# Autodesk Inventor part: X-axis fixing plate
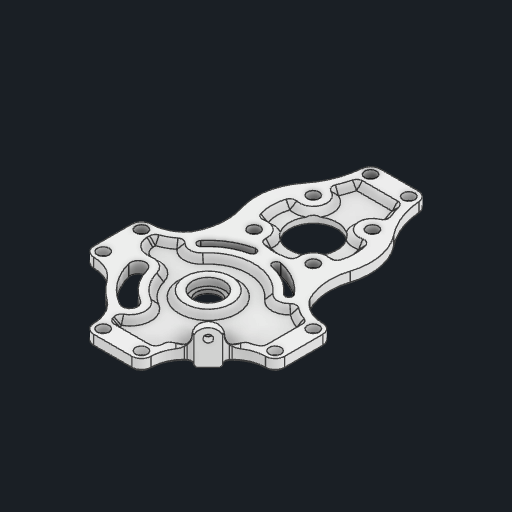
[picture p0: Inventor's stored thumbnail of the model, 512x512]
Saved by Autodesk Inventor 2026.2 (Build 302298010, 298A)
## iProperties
Created: 2026-04
Part Number: X-axis fixing plate
Material: PBT 플라스틱
Document SubType Name: Modeling
Designer: work
Density: 1.31 g/cm^3
Appearance: 매끄러움 - 흰색
Author: work
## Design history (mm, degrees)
sketch "스케치1"
  geometry: L1 (0, 0)-(0, -55); L2 (-15.5, -39.5)-(15.5, -39.5); L3 (15.5, -39.5)-(15.5, -70.5); L4 (15.5, -70.5)-(-15.5, -70.5); L5 (-15.5, -70.5)-(-15.5, -39.5); L6 (-15.5, -39.5)-(15.5, -70.5); L7 (15.5, -39.5)-(-15.5, -70.5); L8 (0, 0)-(22.981, -19.284); L9 (0, 0)-(30, 0); L10 (0, 0)-(6.237, -29.344); L11 (0, 0)-(-6.237, -29.344); L12 (-10, -95)-(10, -95); L13 (0, -55)-(0, -95); L14 (0, 0)-(45, 0); L15 (-10, -95)-(10, -95); L16 (-10, -100)-(10, -100); L17 (10, -90)-(-10, -90); L18 (10, 50)-(-10, 50); L19 (-10, 45)-(10, 45); L20 (-10, 45)-(10, 45); L21 (-10, 40)-(10, 40); L22 (0, 0)-(0, 45); L23 (0, 0)-(-45, 0); L24 (-45, -10)-(-45, 10); L25 (-40, -10)-(-40, 10); L26 (-50, 10)-(-50, -10); L27 (-45, -10)-(-45, 10); L28 (0, 0)-(0, -45); L29 (10, -45)-(-10, -45); L30 (10, -40)-(-10, -40); L31 (-10, -50)-(10, -50); L32 (10, -45)-(-10, -45); L33 (0, 0)-(45, 0); L34 (45, 10)-(45, -10); L35 (40, 10)-(40, -10); L36 (50, -10)-(50, 10); L37 (45, 10)-(45, -10); L38 (0, 0)-(-26.87, 26.87); L39 (-22.627, 31.113)-(-31.113, 22.627); L40 (-31.113, 22.627)-(-28.991, 20.506); L41 (-28.991, 20.506)-(-20.506, 28.991); L42 (-20.506, 28.991)-(-22.627, 31.113); L43 (0, 0)-(28.978, 7.765); L44 (0, 0)-(15, 25.981); C1 r 2.5 at (0, 0); C2 r 8.25 at (0, 0); C3 r 6.25 at (0, 0); C4 r 12.5 at (0, -55); C5 r 2 at (15.5, -39.5); C6 r 2 at (-15.5, -70.5); C7 r 2 at (15.5, -70.5); C8 r 2 at (-15.5, -39.5); C9 r 22 at (0, 0); C10 r 2 at (10, -95); C11 r 2 at (-10, -95); C12 r 2 at (10, 45); C13 r 2 at (-10, 45); C14 r 2 at (-45, 10); C15 r 2 at (-45, -10); C16 r 2 at (-10, -45); C17 r 2 at (10, -45); C18 r 2 at (45, -10); C19 r 2 at (45, 10); A1 r 30 centre (0, 0) between (6.237, -29.344) and (22.981, -19.284); A2 r 32 centre (0, 0) between (6.653, -31.301) and (24.513, -20.569); A3 r 28 centre (0, 0) between (5.822, -27.388) and (21.449, -17.998); A4 r 2 centre (6.237, -29.344) between (5.822, -27.388) and (6.653, -31.301); A5 r 2 centre (22.981, -19.284) between (24.513, -20.569) and (21.449, -17.998); A6 r 28 centre (0, 0) between (-21.449, -17.998) and (-5.822, -27.388); A7 r 30 centre (0, 0) between (-22.981, -19.284) and (-6.237, -29.344); A8 r 2 centre (-6.237, -29.344) between (-6.653, -31.301) and (-5.822, -27.388); A9 r 32 centre (0, 0) between (-24.513, -20.569) and (-6.653, -31.301); A10 r 2 centre (-22.981, -19.284) between (-21.449, -17.998) and (-24.513, -20.569); A11 r 38 centre (0, 0) between (22.258, 30.799) and (-26.87, 26.87); A12 r 30 centre (0, -55) between (-23.514, -73.63) and (28.562, -45.823); A13 r 5 centre (-10, -95) between (-10, -90) and (-10, -100); A14 r 5 centre (10, -95) between (10, -100) and (10, -90); A15 r 40 centre (-54.866, -98.471) between (-14.985, -95.386) and (-23.514, -73.63); A16 r 40 centre (54.866, -98.471) between (23.514, -73.63) and (14.985, -95.386); A17 r 5 centre (-10, 45) between (-10, 50) and (-10, 40); A18 r 5 centre (10, 45) between (10, 40) and (10, 50); A19 r 17.522 centre (32.522, 45) between (15, 45) and (22.258, 30.799); A20 r 17.522 centre (-32.522, 45) between (-22.258, 30.799) and (-15, 45); A21 r 17.522 centre (-45, -32.522) between (-30.799, -22.258) and (-45, -15); A22 r 5 centre (-45, -10) between (-50, -10) and (-40, -10); A23 r 5 centre (-45, 10) between (-40, 10) and (-50, 10); A24 r 17.522 centre (-45, 32.522) between (-45, 15) and (-30.799, 22.258); A25 r 17.522 centre (32.522, -45) between (22.258, -30.799) and (15, -45); A26 r 5 centre (10, -45) between (10, -50) and (10, -40); A27 r 5 centre (-10, -45) between (-10, -40) and (-10, -50); A28 r 17.522 centre (-32.522, -45) between (-15, -45) and (-22.258, -30.799); A29 r 17.522 centre (45, 32.522) between (30.799, 22.258) and (45, 15); A30 r 5 centre (45, 10) between (50, 10) and (40, 10); A31 r 5 centre (45, -10) between (40, -10) and (50, -10); A32 r 17.522 centre (45, -32.522) between (45, -15) and (30.799, -22.258); A33 r 30 centre (57.124, -36.646) between (30.799, -22.258) and (28.562, -45.823); A34 r 30 centre (-57.124, -36.646) between (-28.562, -45.823) and (-30.799, -22.258); A35 r 30 centre (0, 0) between (28.978, 7.765) and (15, 25.981); A36 r 34 centre (0, 0) between (32.841, 8.8) and (17, 29.445); A37 r 26 centre (0, 0) between (25.114, 6.729) and (13, 22.517); A38 r 4 centre (28.978, 7.765) between (25.114, 6.729) and (32.841, 8.8); A39 r 4 centre (15, 25.981) between (17, 29.445) and (13, 22.517); 17 further points
  constraints: 98 end point, 80 point on circle, 58 centre point, 23 coincident, 21 tangent, 14 symmetric about line, 8 midpoint, 7 equal length, 5 horizontal, 5 perpendicular, 3 vertical, 2 point on line, 121 other
  dimensions: "d0" = 5 diameter of C1; "d1" = 16.5 diameter of C2; "d2" = 2 radial gap between concentric circles of C2 C3; "d3" = 55 distance of L1.start L1.end; "d4" = 25 diameter of C4; "d5" = 31 distance of L3.end L4.end; "d6" = 31 distance of L2.end L3.end; "d7" = 4 diameter of C5; "d9" = 4 diameter of C6; "d10" = 4 diameter of C7; "d11" = 4 diameter of C8; "d14" = 44 diameter of C9; "d15" = 30 radius of A1; "d16" = 40 deg angle of L8 L9; "d17" = 38 deg angle of L10 L8; "d18" = 4 diameter of A4; "d19" = 8 radial gap between concentric circles of A11 A1; "d20" = 60 diameter of A12; "d21" = 20 distance of L12.start L12.end; "d22" = 45 distance of L14.start L14.end; "d23" = 40 distance of L13.start L13.end; "d24" = 4 diameter of C10; "d25" = 4 diameter of C11; "d26" = 5 radius of A14; "d27" = 40 radius of A15; "d28" = 20 distance of L20.start L20.end; "d29" = 4 diameter of C12; "d30" = 4 diameter of C13; "d31" = 5 radius of A18; "d32" = 45 distance of L14.start L22.end; "d35" = 360 deg dimension on C9.centre L22.end (derived); "d37" = 30 radius of A33; "d38" = 45 deg angle of L22 L38; "d39" = 12 distance of L40.end L41.end; "d40" = 3 distance of L39.end L40.end; "d41" = 30 radius of A35; "d42" = 45 deg angle of L43 L44; "d43" = 8 diameter of A38; "d44" = 30 deg angle of L22 L44
  node "스케치 - 원형 패턴1" dims "d35" = 360 deg (derived)
extrude "돌출1" new body sketch "스케치1" distance "d45" = 6; taper "d46" = 0 deg
extrude "돌출2" join sketch "스케치1" distance "d47" = 18; taper "d48" = 0 deg
extrude "돌출3" join sketch "스케치1" distance "d49" = 2; taper "d50" = 0 deg
sketch "스케치2"
  geometry: L1 (-50, 10)-(-50, -10) reference; L2 (-10, -50)-(10, -50) reference; L3 (22.29, -30.776)-(20.506, -28.991) reference; L4 (20.506, -28.991)-(28.991, -20.506) reference; L5 (28.991, -20.506)-(30.776, -22.29) reference; L6 (50, -10)-(50, 10) reference; L7 (10, 100)-(-10, 100) reference; C1 r 2 at (10, 95) reference; C2 r 2 at (-10, 95) reference; C3 r 2 at (10, -45) reference; C4 r 2 at (-10, -45) reference; C5 r 2 at (45, 10) reference; C6 r 2 at (45, -10) reference; C7 r 2 at (-45, -10) reference; C8 r 2 at (-45, 10) reference; C9 r 12.5 at (0, 55) reference; C10 r 2 at (-15.5, 39.5) reference; C11 r 2 at (15.5, 70.5) reference; C12 r 2 at (-15.5, 70.5) reference; C13 r 2 at (15.5, 39.5) reference; C14 r 8.25 at (0, 0) reference; A1 r 17.522 centre (-45, 32.522) between (-45, 15) and (-30.799, 22.258) reference; A2 r 5 centre (-45, 10) between (-45, 15) and (-50, 10) reference; A3 r 5 centre (-45, -10) between (-50, -10) and (-45, -15) reference; A4 r 17.522 centre (-45, -32.522) between (-30.799, -22.258) and (-45, -15) reference; A5 r 38 centre (0, 0) between (-30.799, -22.258) and (-22.258, -30.799) reference; A6 r 17.522 centre (-32.522, -45) between (-15, -45) and (-22.258, -30.799) reference; A7 r 5 centre (-10, -45) between (-15, -45) and (-10, -50) reference; A8 r 5 centre (10, -45) between (10, -50) and (15, -45) reference; A9 r 17.522 centre (32.522, -45) between (22.258, -30.799) and (15, -45) reference; A10 r 38 centre (0, 0) between (22.258, -30.799) and (22.29, -30.776) reference; A11 r 38 centre (0, 0) between (30.776, -22.29) and (30.799, -22.258) reference; A12 r 17.522 centre (45, -32.522) between (45, -15) and (30.799, -22.258) reference; A13 r 5 centre (45, -10) between (45, -15) and (50, -10) reference; A14 r 5 centre (45, 10) between (50, 10) and (45, 15) reference; A15 r 17.522 centre (45, 32.522) between (30.799, 22.258) and (45, 15) reference; A16 r 30 centre (57.124, 36.646) between (28.562, 45.823) and (30.799, 22.258) reference; A17 r 30 centre (0, 55) between (28.562, 45.823) and (23.514, 73.63) reference; A18 r 40 centre (54.866, 98.471) between (14.985, 95.386) and (23.514, 73.63) reference; A19 r 5 centre (10, 95) between (14.985, 95.386) and (10, 100) reference; A20 r 5 centre (-10, 95) between (-10, 100) and (-14.985, 95.386) reference; A21 r 40 centre (-54.866, 98.471) between (-23.514, 73.63) and (-14.985, 95.386) reference; A22 r 30 centre (0, 55) between (-23.514, 73.63) and (-28.562, 45.823) reference; A23 r 32 centre (0, 0) between (24.513, 20.569) and (6.653, 31.301) reference; A24 r 2 centre (22.981, 19.284) between (21.449, 17.998) and (24.513, 20.569) reference; A25 r 28 centre (0, 0) between (21.449, 17.998) and (5.822, 27.388) reference; A26 r 2 centre (6.237, 29.344) between (6.653, 31.301) and (5.822, 27.388) reference; A27 r 32 centre (0, 0) between (-6.653, 31.301) and (-24.513, 20.569) reference; A28 r 2 centre (-6.237, 29.344) between (-5.822, 27.388) and (-6.653, 31.301) reference; A29 r 28 centre (0, 0) between (-5.822, 27.388) and (-21.449, 17.998) reference; A30 r 2 centre (-22.981, 19.284) between (-24.513, 20.569) and (-21.449, 17.998) reference; A31 r 26 centre (0, 0) between (-25.114, -6.729) and (-13, -22.517) reference; A32 r 4 centre (-15, -25.981) between (-17, -29.445) and (-13, -22.517) reference; A33 r 34 centre (0, 0) between (-32.841, -8.8) and (-17, -29.445) reference; A34 r 4 centre (-28.978, -7.765) between (-25.114, -6.729) and (-32.841, -8.8) reference; A35 r 30 centre (-57.124, 36.646) between (-30.799, 22.258) and (-28.562, 45.823) reference; 11 further points
  constraints: 10 coincident
hole "구멍1" sketch "스케치2" at (-10, -45), (10, -45), (-45, -10), (-45, 10), (15.5, 39.5), (-15.5, 39.5), (15.5, 70.5), (-15.5, 70.5), (10, 95), (-10, 95), (45, 10), (45, -10) diameter "d51" = 4; stored, may be unused: countersink angle "d55" = 90 deg, drill point angle "d57" = 0 deg; dims "d52" = 6, "d53" = 6.2, "d54" = 4, "d56" = 8
sketch "스케치3"
  geometry: L1 (-6, 0)-(-6, 18); L2 (-12, 18)-(0, 18) reference; C1 r 2 at (-6, 13)
  constraints: 2 end point, 1 centre point, 1 midpoint, 1 point on line
  dimensions: "d58" = 4 diameter of C1; "d59" = 5 distance from line of L2 C1.centre
extrude "돌출4" cut sketch "스케치3" distance "d60" = 6; taper "d61" = 0 deg
fillet "모깎기1" dims "d62" = 6
sketch "스케치4"
  geometry: L1 (16.263, -33.234)-(18.091, -35.062) reference; L2 (16.263, -33.234)-(33.234, -16.263) reference; L3 (35.062, -18.091)-(33.234, -16.263) reference; L4 (50, -10)-(50, 10) reference; L5 (10, 100)-(-10, 100) reference; L6 (-50, 10)-(-50, -10) reference; L7 (-10, -50)-(10, -50) reference; L8 (-10, 96)-(10, 96); L9 (46, 10)-(46, -10); L10 (35.727, -13.1)-(33.234, -10.607); L11 (33.234, -10.607)-(10.607, -33.234); L12 (10.607, -33.234)-(13.1, -35.727); L13 (10, -46)-(-10, -46); L14 (-46, -10)-(-46, 10); L15 (-10, -45)-(10, -45); L16 (-10, -40)-(10, -40); L17 (10, -50)-(-10, -50); L18 (-45, -10)-(-45, 10); L19 (-40, -10)-(-40, 10); L20 (-50, 10)-(-50, -10); L21 (45, -10)-(45, 10); L22 (50, -10)-(50, 10); L23 (40, 10)-(40, -10); L24 (10, 95)-(-10, 95); L25 (10, 100)-(-10, 100); L26 (-10, 90)-(10, 90); L27 (0, 55)-(0, 0); C1 r 6.25 at (0, 0) reference; C2 r 12.25 at (0, 0); C3 r 8.25 at (0, 0) reference; C4 r 8.25 at (0, 0) reference; C5 r 12.5 at (0, 55) reference; C6 r 3.1 at (-10, -45) reference; C7 r 3.1 at (10, -45) reference; C8 r 3.1 at (-45, -10) reference; C9 r 3.1 at (-45, 10) reference; C10 r 3.1 at (15.5, 39.5) reference; C11 r 3.1 at (-15.5, 39.5) reference; C12 r 3.1 at (15.5, 70.5) reference; C13 r 3.1 at (-15.5, 70.5) reference; C14 r 3.1 at (10, 95) reference; C15 r 3.1 at (-10, 95) reference; C16 r 3.1 at (45, 10) reference; C17 r 3.1 at (45, -10) reference; C18 r 36 at (0, 0); C19 r 7.1 at (-15.5, 39.5); C20 r 7.1 at (-15.5, 70.5); C21 r 7.1 at (15.5, 70.5); C22 r 2 at (-10, -45) reference; C23 r 2 at (-45, -10) reference; A1 r 26 centre (0, 0) between (-25.114, -6.729) and (-13, -22.517) reference; A2 r 4 centre (-15, -25.981) between (-17, -29.445) and (-13, -22.517) reference; A3 r 34 centre (0, 0) between (-32.841, -8.8) and (-17, -29.445) reference; A4 r 4 centre (-28.978, -7.765) between (-25.114, -6.729) and (-32.841, -8.8) reference; A5 r 32 centre (0, 0) between (-6.653, 31.301) and (-24.513, 20.569) reference; A6 r 2 centre (-6.237, 29.344) between (-5.822, 27.388) and (-6.653, 31.301) reference; A7 r 28 centre (0, 0) between (-5.822, 27.388) and (-21.449, 17.998) reference; A8 r 2 centre (-22.981, 19.284) between (-24.513, 20.569) and (-21.449, 17.998) reference; A9 r 32 centre (0, 0) between (24.513, 20.569) and (6.653, 31.301) reference; A10 r 2 centre (22.981, 19.284) between (21.449, 17.998) and (24.513, 20.569) reference; A11 r 28 centre (0, 0) between (21.449, 17.998) and (5.822, 27.388) reference; A12 r 2 centre (6.237, 29.344) between (6.653, 31.301) and (5.822, 27.388) reference; A13 r 17.522 centre (45, -32.522) between (45, -15) and (35.062, -18.091) reference; A14 r 5 centre (45, -10) between (45, -15) and (50, -10) reference; A15 r 5 centre (45, 10) between (50, 10) and (45, 15) reference; A16 r 17.522 centre (45, 32.522) between (30.799, 22.258) and (45, 15) reference; A17 r 30 centre (57.124, 36.646) between (28.562, 45.823) and (30.799, 22.258) reference; A18 r 30 centre (0, 55) between (28.562, 45.823) and (23.514, 73.63) reference; A19 r 40 centre (54.866, 98.471) between (14.985, 95.386) and (23.514, 73.63) reference; A20 r 5 centre (10, 95) between (14.985, 95.386) and (10, 100) reference; A21 r 5 centre (-10, 95) between (-10, 100) and (-14.985, 95.386) reference; A22 r 40 centre (-54.866, 98.471) between (-23.514, 73.63) and (-14.985, 95.386) reference; A23 r 30 centre (0, 55) between (-23.514, 73.63) and (-28.562, 45.823) reference; A24 r 30 centre (-57.124, 36.646) between (-30.799, 22.258) and (-28.562, 45.823) reference; A25 r 17.522 centre (-45, 32.522) between (-45, 15) and (-30.799, 22.258) reference; A26 r 5 centre (-45, 10) between (-45, 15) and (-50, 10) reference; A27 r 5 centre (-45, -10) between (-50, -10) and (-45, -15) reference; A28 r 17.522 centre (-45, -32.522) between (-30.799, -22.258) and (-45, -15) reference; A29 r 38 centre (0, 0) between (-30.799, -22.258) and (-22.258, -30.799) reference; A30 r 17.522 centre (-32.522, -45) between (-15, -45) and (-22.258, -30.799) reference; A31 r 5 centre (-10, -45) between (-15, -45) and (-10, -50) reference; A32 r 5 centre (10, -45) between (10, -50) and (15, -45) reference; A33 r 17.522 centre (32.522, -45) between (18.091, -35.062) and (15, -45) reference; A34 r 22 centre (0, 0) between (-21.25, -5.694) and (-11, -19.053); A35 r 8 centre (-28.978, -7.765) between (-21.25, -5.694) and (-36.705, -9.835); A36 r 38 centre (0, 0) between (-36.705, -9.835) and (-19, -32.909); A37 r 8 centre (-15, -25.981) between (-19, -32.909) and (-11, -19.053); A38 r 36 centre (0, 0) between (-7.485, 35.213) and (-27.578, 23.14); A39 r 6 centre (-6.237, 29.344) between (-4.99, 23.476) and (-7.485, 35.213); A40 r 24 centre (0, 0) between (-4.99, 23.476) and (-18.385, 15.427); A41 r 6 centre (-22.981, 19.284) between (-27.578, 23.14) and (-18.385, 15.427); A42 r 24 centre (0, 0) between (18.385, 15.427) and (4.99, 23.476); A43 r 6 centre (22.981, 19.284) between (18.385, 15.427) and (27.578, 23.14); A44 r 36 centre (0, 0) between (27.578, 23.14) and (7.485, 35.213); A45 r 6 centre (6.237, 29.344) between (7.485, 35.213) and (4.99, 23.476); A46 r 21.92 centre (0, 55) between (-15.5, 39.5) and (19.641, 45.267); A47 r 26 centre (0, 55) between (-20.379, 71.146) and (-24.754, 47.046); A48 r 44 centre (-54.866, 98.471) between (-20.379, 71.146) and (-10.997, 95.077); A49 r 1 centre (-10, 95) between (-10, 96) and (-10.997, 95.077); A50 r 1 centre (10, 95) between (10.997, 95.077) and (10, 96); A51 r 44 centre (54.866, 98.471) between (10.997, 95.077) and (20.379, 71.146); A52 r 26 centre (0, 55) between (24.754, 47.046) and (20.379, 71.146); A53 r 34 centre (57.124, 36.646) between (24.754, 47.046) and (27.408, 20.124); A54 r 21.522 centre (45, 32.522) between (27.408, 20.124) and (45, 11); A55 r 1 centre (45, 10) between (46, 10) and (45, 11); A56 r 1 centre (45, -10) between (45, -11) and (46, -10); A57 r 21.522 centre (45, -32.522) between (45, -11) and (35.727, -13.1); A58 r 21.522 centre (32.522, -45) between (13.1, -35.727) and (11, -45); A59 r 1 centre (10, -45) between (10, -46) and (11, -45); A60 r 1 centre (-10, -45) between (-11, -45) and (-10, -46); A61 r 21.522 centre (-32.522, -45) between (-11, -45) and (-19.915, -27.557); A62 r 34 centre (0, 0) between (-27.557, -19.915) and (-19.915, -27.557); A63 r 21.522 centre (-45, -32.522) between (-27.557, -19.915) and (-45, -11); A64 r 1 centre (-45, -10) between (-46, -10) and (-45, -11)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; 31 further points
  constraints: 89 point on circle, 49 centre point, 48 end point, 17 tangent, 7 parallel, 4 midpoint, 3 coincident, 3 symmetric about line, 2 vertical, 41 other
  dimensions: "d63" = 4 radial gap between concentric circles of C2 C3; "d64" = 0 radial gap between concentric circles of A29 A36; "d65" = 4 radial gap between concentric circles of A5 A38; "d66" = 72 diameter of C18; "d67" = 4 radial gap between concentric circles of A12 A45; "d68" = 4 radial gap between concentric circles of C11 C19; "d69" = 4 radial gap between concentric circles of C13 C20; "d70" = 4 radial gap between concentric circles of C12 C21; "d71" = 4 dimension on C10; "d72" = 4 radial gap between concentric circles of A23 A47; "d73" = 5 radius of A68; "d74" = 10 diameter of A71; "d75" = 10 diameter of A73; "d76" = 10 diameter of A75
extrude "돌출5" cut sketch "스케치4" distance "d77" = 3; taper "d78" = 0 deg
fillet "모깎기2" dims "d79" = 3
sketch "스케치5"
  geometry: L1 (40, 9.342)-(40, -9.342) reference; L2 (-9.287, 90)-(9.287, 90) reference; L3 (-40, -10)-(-40, 9.342) reference; L4 (9.342, -40)-(-9.342, -40) reference; L5 (30.45, -19.048)-(19.048, -30.45) reference; C1 r 12.5 at (0, 55) reference; C2 r 12.25 at (0, 0) reference; C3 r 20.403 at (0, 55); A1 r 6 centre (6.237, 29.344) between (5.726, 35.323) and (4.99, 23.476) reference; A2 r 3 centre (35.043, -10.113) between (35.284, -13.103) and (36.261, -12.854) reference; A3 r 21.522 centre (45, -32.522) between (37.979, -12.178) and (36.261, -12.854) reference; A4 r 3 centre (37, -9.342) between (37.979, -12.178) and (40, -9.342) reference; A5 r 3 centre (37, 9.342) between (40, 9.342) and (37.979, 12.178) reference; A6 r 21.522 centre (45, 32.522) between (31.601, 15.68) and (37.979, 12.178) reference; A7 r 3 centre (29.733, 13.332) between (31.601, 15.68) and (27.482, 15.316) reference; A8 r 6 centre (22.981, 19.284) between (18.385, 15.427) and (27.482, 15.316) reference; A9 r 24 centre (0, 0) between (18.385, 15.427) and (4.99, 23.476) reference; A10 r 6 centre (6.237, 29.344) between (5.726, 35.323) and (4.99, 23.476) reference; A11 r 3 centre (5.47, 38.312) between (5.726, 35.323) and (8.449, 38.665) reference; A12 r 7.1 centre (15.5, 39.5) between (17.281, 46.373) and (8.449, 38.665) reference; A13 r 3 centre (18.034, 49.277) between (17.281, 46.373) and (20.893, 48.37) reference; A14 r 21.92 centre (0, 55) between (20.893, 48.37) and (20.893, 61.63) reference; A15 r 3 centre (18.034, 60.723) between (20.893, 61.63) and (17.281, 63.627) reference; A16 r 7.1 centre (15.5, 70.5) between (12.834, 77.08) and (17.281, 63.627) reference; A17 r 3 centre (11.707, 79.861) between (12.834, 77.08) and (14.462, 81.049) reference; A18 r 44 centre (54.866, 98.471) between (12.197, 87.732) and (14.462, 81.049) reference; A19 r 3 centre (9.287, 87) between (12.197, 87.732) and (9.287, 90) reference; A20 r 3 centre (-9.287, 87) between (-9.287, 90) and (-12.197, 87.732) reference; A21 r 44 centre (-54.866, 98.471) between (-14.462, 81.049) and (-12.197, 87.732) reference; A22 r 3 centre (-11.707, 79.861) between (-14.462, 81.049) and (-12.834, 77.08) reference; A23 r 7.1 centre (-15.5, 70.5) between (-17.281, 63.627) and (-12.834, 77.08) reference; A24 r 3 centre (-18.034, 60.723) between (-17.281, 63.627) and (-20.893, 61.63) reference; A25 r 21.92 centre (0, 55) between (-20.893, 61.63) and (-20.893, 48.37) reference; A26 r 3 centre (-18.034, 49.277) between (-20.893, 48.37) and (-17.281, 46.373) reference; A27 r 7.1 centre (-15.5, 39.5) between (-8.449, 38.665) and (-17.281, 46.373) reference; A28 r 3 centre (-5.47, 38.312) between (-8.449, 38.665) and (-5.726, 35.323) reference; A29 r 6 centre (-6.237, 29.344) between (-4.99, 23.476) and (-5.726, 35.323) reference; A30 r 24 centre (0, 0) between (-4.99, 23.476) and (-18.385, 15.427) reference; A31 r 6 centre (-22.981, 19.284) between (-27.482, 15.316) and (-18.385, 15.427) reference; A32 r 3 centre (-29.733, 13.332) between (-27.482, 15.316) and (-31.601, 15.68) reference; A33 r 21.522 centre (-45, 32.522) between (-37.979, 12.178) and (-31.601, 15.68) reference; A34 r 3 centre (-37, 9.342) between (-37.979, 12.178) and (-40, 9.342) reference; A35 r 8 centre (-28.978, -7.765) between (-21.25, -5.694) and (-36.705, -9.835) reference; A36 r 22 centre (0, 0) between (-21.25, -5.694) and (-11, -19.053) reference; A37 r 8 centre (-15, -25.981) between (-11.244, -33.044) and (-11, -19.053) reference; A38 r 3 centre (-9.835, -35.693) between (-11.244, -33.044) and (-12.61, -36.831) reference; A39 r 21.522 centre (-32.522, -45) between (-12.178, -37.979) and (-12.61, -36.831) reference; A40 r 3 centre (-9.342, -37) between (-12.178, -37.979) and (-9.342, -40) reference; A41 r 3 centre (9.342, -37) between (9.342, -40) and (12.178, -37.979) reference; A42 r 21.522 centre (32.522, -45) between (12.36, -37.47) and (12.178, -37.979) reference; A43 r 3 centre (9.55, -36.42) between (12.36, -37.47) and (12.533, -36.1) reference; A44 r 3 centre (15.516, -35.781) between (14.322, -33.028) and (12.533, -36.1) reference; A45 r 36 centre (0, 0) between (14.322, -33.028) and (18.465, -30.904) reference; A46 r 3 centre (16.927, -28.328) between (18.465, -30.904) and (19.048, -30.45) reference; A47 r 3 centre (28.328, -16.927) between (30.45, -19.048) and (30.904, -18.465) reference; A48 r 36 centre (0, 0) between (30.904, -18.465) and (32.792, -14.855) reference; A49 r 3 centre (35.525, -16.093) between (35.284, -13.103) and (32.792, -14.855) reference; A50 r 21.522 centre (-45, -32.522) between (-35.658, -13.133) and (-40.241, -11.533) reference; A51 r 38 centre (0, 0) between (-36.705, -9.835) and (-35.658, -13.133) reference; A52 r 5 centre (-45, -10) between (-40.241, -11.533) and (-40, -10) reference; 5 further points
  constraints: 2 coincident, 1 centre point, 1 tangent, 3 other
extrude "돌출6" join sketch "스케치5" distance "d80" = 3; taper "d81" = 0 deg
sketch "스케치6"
  geometry: L1 (-40, -10)-(-40, 9.342) reference; L2 (-40, -10)-(-40, 9.342) reference; L3 (-40, -10)-(-40, 9.342) reference; L4 (9.342, -40)-(-9.342, -40) reference; L5 (30.45, -19.048)-(19.048, -30.45) reference; L6 (40, 9.342)-(40, -9.342) reference; C1 r 12.25 at (0, 0) reference; A1 r 8 centre (-28.978, -7.765) between (-21.25, -5.694) and (-36.705, -9.835) reference; A2 r 8 centre (-32, 7.947) between (-40, 7.947) and (-30.489, 0.091); A3 r 24 centre (0, 0) between (18.385, 15.427) and (-18.385, 15.427) reference; A4 r 6 centre (-22.981, 19.284) between (-27.482, 15.316) and (-18.385, 15.427) reference; A5 r 3 centre (-29.733, 13.332) between (-27.482, 15.316) and (-31.601, 15.68) reference; A6 r 21.522 centre (-45, 32.522) between (-37.979, 12.178) and (-31.601, 15.68) reference; A7 r 3 centre (-37, 9.342) between (-37.979, 12.178) and (-40, 9.342) reference; A8 r 5 centre (-45, -10) between (-40.241, -11.533) and (-40, -10) reference; A9 r 21.522 centre (-45, -32.522) between (-35.658, -13.133) and (-40.241, -11.533) reference; A10 r 38 centre (0, 0) between (-36.705, -9.835) and (-35.658, -13.133) reference; A11 r 8 centre (-28.978, -7.765) between (-21.25, -5.694) and (-36.705, -9.835) reference; A12 r 22 centre (0, 0) between (-21.25, -5.694) and (-11, -19.053) reference; A13 r 8 centre (-15, -25.981) between (-11.244, -33.044) and (-11, -19.053) reference; A14 r 3 centre (-9.835, -35.693) between (-11.244, -33.044) and (-12.61, -36.831) reference; A15 r 21.522 centre (-32.522, -45) between (-12.178, -37.979) and (-12.61, -36.831) reference; A16 r 3 centre (-9.342, -37) between (-12.178, -37.979) and (-9.342, -40) reference; A17 r 3 centre (9.342, -37) between (9.342, -40) and (12.178, -37.979) reference; A18 r 21.522 centre (32.522, -45) between (12.36, -37.47) and (12.178, -37.979) reference; A19 r 3 centre (9.55, -36.42) between (12.36, -37.47) and (12.533, -36.1) reference; A20 r 3 centre (15.516, -35.781) between (14.322, -33.028) and (12.533, -36.1) reference; A21 r 36 centre (0, 0) between (14.322, -33.028) and (18.465, -30.904) reference; A22 r 3 centre (16.927, -28.328) between (18.465, -30.904) and (19.048, -30.45) reference; A23 r 3 centre (28.328, -16.927) between (30.45, -19.048) and (30.904, -18.465) reference; A24 r 36 centre (0, 0) between (30.904, -18.465) and (32.792, -14.855) reference; A25 r 3 centre (35.525, -16.093) between (35.284, -13.103) and (32.792, -14.855) reference; A26 r 3 centre (35.043, -10.113) between (35.284, -13.103) and (36.261, -12.854) reference; A27 r 21.522 centre (45, -32.522) between (37.979, -12.178) and (36.261, -12.854) reference; A28 r 3 centre (37, -9.342) between (37.979, -12.178) and (40, -9.342) reference; A29 r 3 centre (37, 9.342) between (40, 9.342) and (37.979, 12.178) reference; A30 r 21.522 centre (45, 32.522) between (31.601, 15.68) and (37.979, 12.178) reference; A31 r 3 centre (29.733, 13.332) between (31.601, 15.68) and (27.482, 15.316) reference; A32 r 6 centre (22.981, 19.284) between (18.385, 15.427) and (27.482, 15.316) reference; 3 further points
  constraints: 3 point on circle, 2 tangent, 1 centre point, 1 point on line
  dimensions: "d85" = 8 radius of A2
extrude "돌출7" join sketch "스케치6" distance "d86" = 3; taper "d87" = 0 deg
chamfer "모따기2" distance "d88" = 3; stored, may be unused: second distance "d89" = 2, angle "d90" = 45 deg
sketch "스케치7"
  geometry: L1 (0, 14.756)-(0, 0) reference; L2 (-10.659, 0)-(-10.659, 14.756) reference; L3 (-10.659, 0)-(0, 0) reference; C1 r 2 at (-5.33, 13) reference; A1 r 6 centre (-5.33, 12) between (0, 14.756) and (-10.659, 14.756) reference; 1 further point
extrude "돌출8" join sketch "스케치7" distance "d91" = 3; taper "d92" = 0 deg
fillet "모깎기3" dims "d93" = 3
sketch "스케치8"
  geometry: L1 (8.062, -6)-(-8.062, -6) reference; L2 (12, -6)-(8.062, -6) reference; L3 (-8.062, -6)-(-12, -6) reference; C1 r 2 at (0, 1) reference; A1 r 6 centre (12, 0) between (6, 0) and (12, -6) reference; A2 r 6 centre (0, 0) between (6, 0) and (-6, 0) reference; A3 r 6 centre (-12, 0) between (-12, -6) and (-6, 0) reference; 1 further point
extrude "돌출9" cut sketch "스케치8" distance "d94" = 2; taper "d95" = 0 deg
fillet "모깎기4" dims "d96" = 3
chamfer "모따기3" distance "d97" = 3; stored, may be unused: second distance "d98" = 2, angle "d99" = 45 deg
chamfer "모따기4" distance "d100" = 1; stored, may be unused: second distance "d101" = 2, angle "d102" = 45 deg
sketch "스케치9"
  geometry: L1 (32.053, 25.93)-(31.583, 25.46) reference; L2 (25.93, 32.053)-(32.053, 25.93) reference; L3 (25.46, 31.583)-(25.93, 32.053) reference; L4 (-10, 49)-(10, 49) reference; L5 (-49, -10)-(-49, 10) reference; L6 (10, -99)-(-10, -99) reference; L7 (49, 10)-(49, -10) reference; C1 r 6.25 at (0, 0) reference; C2 r 2 at (10, -95) reference; C3 r 2 at (-10, -95) reference; C4 r 2 at (10, 45) reference; C5 r 2 at (-10, 45) reference; C6 r 2 at (45, -10) reference; C7 r 2 at (45, 10) reference; C8 r 2 at (-45, 10) reference; C9 r 2 at (-45, -10) reference; C10 r 12.5 at (0, -55) reference; C11 r 2 at (-15.5, -39.5) reference; C12 r 2 at (15.5, -70.5) reference; C13 r 2 at (-15.5, -70.5) reference; C14 r 2 at (15.5, -39.5) reference; A1 r 4 centre (22.631, 34.411) between (20.306, 31.156) and (25.46, 31.583) reference; A2 r 7 centre (24.375, 36.853) between (19.425, 31.903) and (20.306, 31.156) reference; A3 r 18.522 centre (32.522, 45) between (14, 45) and (19.425, 31.903) reference; A4 r 4 centre (10, 45) between (14, 45) and (10, 49) reference; A5 r 4 centre (-10, 45) between (-10, 49) and (-14, 45) reference; A6 r 18.522 centre (-32.522, 45) between (-21.673, 29.988) and (-14, 45) reference; A7 r 37 centre (0, 0) between (-21.673, 29.988) and (-29.988, 21.673) reference; A8 r 18.522 centre (-45, 32.522) between (-45, 14) and (-29.988, 21.673) reference; A9 r 4 centre (-45, 10) between (-45, 14) and (-49, 10) reference; A10 r 4 centre (-45, -10) between (-49, -10) and (-45, -14) reference; A11 r 18.522 centre (-45, -32.522) between (-30.128, -21.482) and (-45, -14) reference; A12 r 4 centre (-33.339, -23.867) between (-29.816, -21.973) and (-30.128, -21.482) reference; A13 r 31 centre (-57.124, -36.646) between (-27.61, -46.129) and (-29.816, -21.973) reference; A14 r 29 centre (0, -55) between (-27.61, -46.129) and (-22.73, -73.009) reference; A15 r 41 centre (-54.866, -98.471) between (-13.988, -95.309) and (-22.73, -73.009) reference; A16 r 4 centre (-10, -95) between (-13.988, -95.309) and (-10, -99) reference; A17 r 4 centre (10, -95) between (10, -99) and (13.988, -95.309) reference; A18 r 41 centre (54.866, -98.471) between (22.73, -73.009) and (13.988, -95.309) reference; A19 r 29 centre (0, -55) between (22.73, -73.009) and (27.61, -46.129) reference; A20 r 31 centre (57.124, -36.646) between (29.816, -21.973) and (27.61, -46.129) reference; A21 r 4 centre (33.339, -23.867) between (30.128, -21.482) and (29.816, -21.973) reference; A22 r 18.522 centre (45, -32.522) between (45, -14) and (30.128, -21.482) reference; A23 r 4 centre (45, -10) between (45, -14) and (49, -10) reference; A24 r 4 centre (45, 10) between (49, 10) and (45, 14) reference; A25 r 18.522 centre (45, 32.522) between (31.903, 19.425) and (45, 14) reference; A26 r 7 centre (36.853, 24.375) between (31.156, 20.306) and (31.903, 19.425) reference; A27 r 4 centre (34.411, 22.631) between (31.583, 25.46) and (31.156, 20.306) reference; A28 r 32 centre (0, 0) between (6.653, -31.301) and (24.513, -20.569) reference; A29 r 2 centre (6.237, -29.344) between (5.822, -27.388) and (6.653, -31.301) reference; A30 r 28 centre (0, 0) between (5.822, -27.388) and (21.449, -17.998) reference; A31 r 2 centre (22.981, -19.284) between (24.513, -20.569) and (21.449, -17.998) reference; A32 r 32 centre (0, 0) between (-24.513, -20.569) and (-6.653, -31.301) reference; A33 r 2 centre (-22.981, -19.284) between (-21.449, -17.998) and (-24.513, -20.569) reference; A34 r 28 centre (0, 0) between (-21.449, -17.998) and (-5.822, -27.388) reference; A35 r 2 centre (-6.237, -29.344) between (-6.653, -31.301) and (-5.822, -27.388) reference; A36 r 26 centre (0, 0) between (-13, 22.517) and (-25.114, 6.729) reference; A37 r 4 centre (-28.978, 7.765) between (-32.841, 8.8) and (-25.114, 6.729) reference; A38 r 34 centre (0, 0) between (-17, 29.445) and (-32.841, 8.8) reference; A39 r 4 centre (-15, 25.981) between (-13, 22.517) and (-17, 29.445) reference; 1 further point
  node "투영된 루프7"
feature "ӟ耀Ӣ耀ӥ耀Ө耀ӫ耀Ӯ耀ӱ耀Ӵ耀" dims "d0" = 5, "d1" = 16.5, "d2" = 2, "d3" = 55, "d4" = 25, "d5" = 31, "d6" = 31, "d7" = 4, "d9" = 4, "d10" = 4, "d11" = 4, "d14" = 44, "d15" = 30, "d16" = 40 deg, "d17" = 38 deg, "d18" = 4, "d19" = 8, "d20" = 60, "d21" = 20, "d22" = 45, "d23" = 40, "d24" = 4, "d25" = 4, "d26" = 5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
node "솔리드1"
node "투영된 루프1"
node "투영된 루프2"
node "투영된 루프3"
node "투영된 루프4"
node "투영된 루프5"
node "투영된 루프6"
feature "A9D066F2-1C7D-4E18-AEED-F7BC21143FA4" dims "d51" = 4, "d52" = 6, "d53" = 6.2, "d54" = 4, "d55" = 90 deg, "d56" = 8, "d57" = 0
